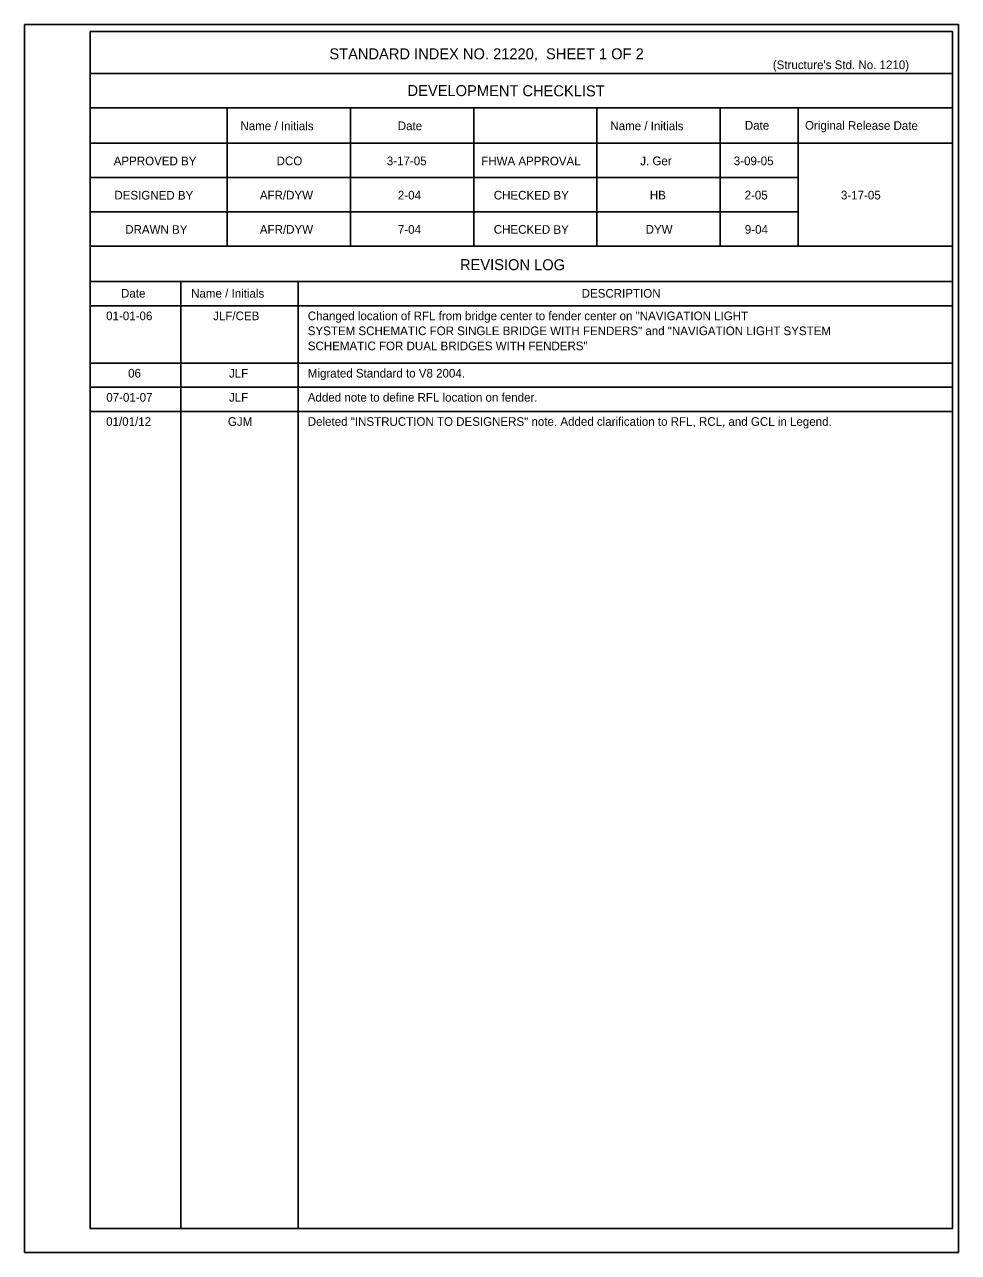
# Model space of a CAD drawing. Extents: x 84082 to 86787, y 72619 to 74101.
# Drawn here: x 85969 to 86787, y 73026 to 74101 of the extents above; entities that cross this region are included whole.
import ezdxf

# ---------------------------------------------------------------- set-up
doc = ezdxf.new("R2010")
doc.units = 0
for name, color, linetype in [('Border', 7, 'Continuous'), ('PlotBorder_dp', 7, 'Continuous'), ('TextStructures', 7, 'Continuous')]:
    doc.layers.add(name, color=color, linetype=linetype)

msp = doc.modelspace()

# ---------------------------------------------------------------- linework, layer by layer
at = {"layer": 'Border'}
for p, q in [((86781.7, 74058), (86026.2, 74058)), ((86781.7, 74028), (86026.2, 74028)), ((86146.2, 74028), (86146.2, 73906.9)), ((86254.2, 74028), (86254.2, 73906.9)), ((86362.2, 74028), (86362.2, 73906.9)), ((86470.2, 74028), (86470.2, 73906.9)), ((86578.2, 74028), (86578.2, 73906.9)), ((86646.3, 74028), (86646.3, 73906.9)), ((86781.7, 73996.9), (86026.2, 73996.9)), ((86646.3, 73966.9), (86026.2, 73966.9)), ((86646.3, 73936.9), (86026.2, 73936.9)), ((86781.7, 73906.9), (86026.2, 73906.9)), ((86781.7, 73875.9), (86026.2, 73875.9)), ((86105.7, 73875.9), (86105.7, 73046.9)), ((86208.5, 73875.9), (86208.5, 73046.9)), ((86781.7, 73854.7), (86026.2, 73854.7)), ((86781.7, 73804.5), (86026.2, 73804.5)), ((86781.7, 73783.4), (86026.2, 73783.4)), ((86781.7, 73762.2), (86026.2, 73762.2))]:
    msp.add_line(p, q, dxfattribs=at)
msp.add_lwpolyline([(86026.2, 74094.7), (86781.7, 74094.7), (86781.7, 73046.9), (86026.2, 73046.9)], close=True, dxfattribs=at)
at = {"layer": 'PlotBorder_dp'}
msp.add_line((85968.8, 73025.8), (85968.8, 73025.8), dxfattribs=at)
msp.add_lwpolyline([(85968.8, 74100.8), (86786.8, 74100.8), (86786.8, 73025.8), (85968.8, 73025.8)], close=True, dxfattribs=at)

# ---------------------------------------------------------------- texts
at = {"layer": 'TextStructures'}
for s, height, p in [('STANDARD INDEX NO. 21220,  SHEET 1 OF 2', 9.6, (86235.8, 74070.4)), ("(Structure's Std. No. 1210)", 7.56, (86624.2, 74061.8)), ('DCO', 7.56, (86189.6, 73977.7)), ('3-17-05', 7.56, (86286.1, 73977.7)), ('J. Ger', 7.56, (86508.1, 73977.7)), ('3-09-05', 7.56, (86590, 73977.7)), ('AFR/DYW', 7.56, (86174.9, 73947.7)), ('2-04', 7.56, (86295.8, 73947.7)), ('HB', 7.56, (86516.5, 73947.7)), ('2-05', 7.56, (86599.5, 73947.7)), ('3-17-05', 7.56, (86683.9, 73947.7)), ('AFR/DYW', 7.56, (86174.9, 73917.7)), ('7-04', 7.56, (86295.8, 73917.7)), ('DYW', 7.56, (86512.8, 73917.7)), ('9-04', 7.56, (86599.7, 73917.7)), ('DESCRIPTION', 7.56, (86456.8, 73861.7)), ('01-01-06', 7.56, (86040.3, 73842)), ('JLF/CEB', 7.56, (86134, 73842)), ('Changed location of RFL from bridge center to fender center on "NAVIGATION LIGHT', 7.56, (86216.9, 73842)), ('SYSTEM SCHEMATIC FOR SINGLE BRIDGE WITH FENDERS" and "NAVIGATION LIGHT SYSTEM', 7.56, (86216.9, 73828.9)), ('SCHEMATIC FOR DUAL BRIDGES WITH FENDERS"', 7.56, (86216.9, 73815.7)), ('06', 7.56, (86059.5, 73791.8)), ('JLF', 7.56, (86147.9, 73791.8)), ('Migrated Standard to V8 2004.', 7.56, (86216.9, 73791.8)), ('07-01-07', 7.56, (86040.4, 73770.7)), ('JLF', 7.56, (86147.9, 73770.7)), ('Added note to define RFL location on fender.', 7.56, (86216.9, 73770.7)), ('01/01/12', 7.56, (86040.3, 73749.5)), ('GJM', 7.56, (86146.9, 73749.5)), ('Deleted "INSTRUCTION TO DESIGNERS" note. Added clarification to RFL, RCL, and GCL in Legend.', 7.56, (86216.9, 73749.5))]:
    msp.add_text(s, height=height, dxfattribs=at).set_placement(p)
for s, height, p in [('DEVELOPMENT CHECKLIST', 9.6, (86304.3, 74038.3)), ('Name / Initials', 7.56, (86157.9, 74008.4)), ('Date', 7.56, (86295.7, 74008.4)), ('Name / Initials', 7.56, (86481.9, 74008.4)), ('Date', 7.56, (86599.7, 74008.8)), ('Original Release Date', 7.56, (86652.4, 74008.8)), ('APPROVED BY', 7.56, (86046.9, 73977.7)), ('FHWA APPROVAL', 7.56, (86368.8, 73977.7)), ('DESIGNED BY', 7.56, (86047.5, 73947.7)), ('CHECKED BY', 7.56, (86379.8, 73947.7)), ('DRAWN BY', 7.56, (86057, 73917.7)), ('CHECKED BY', 7.56, (86379.8, 73917.7)), ('REVISION LOG', 9.6, (86350.2, 73885.9)), ('Date', 7.56, (86053.3, 73861.8)), ('Name / Initials', 7.56, (86114.7, 73861.8))]:
    msp.add_text(s, height=height, rotation=359.8756, dxfattribs=at).set_placement(p)

doc.saveas('drawing.dxf')
